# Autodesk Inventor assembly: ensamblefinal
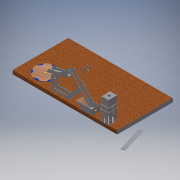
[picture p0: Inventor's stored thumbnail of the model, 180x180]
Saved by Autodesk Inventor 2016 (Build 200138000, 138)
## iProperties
Created: 2016-06
Part Number: ensamblefinal
Material: Genérico
Document SubType Name: Assembly
Designer: adm
Author: adm
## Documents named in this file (13)
- C:\Users\adm\Desktop\el ultimo\ensamblefinal.iam
- C:\Users\adm\Desktop\el ultimo\SOPORTE1.ipt
- C:\Users\adm\Desktop\el ultimo\soporte de rodillos(7.5mm).ipt
- C:\Users\adm\Desktop\el ultimo\soporte3s.ipt
- C:\Users\adm\Desktop\el ultimo\soporte2 de faja.ipt
- C:\Users\adm\Desktop\el ultimo\tablero.ipt
- C:\Users\adm\Desktop\el ultimo\rampa.ipt
- C:\Users\adm\Desktop\el ultimo\caja de motor de faja.ipt
- C:\Users\adm\Desktop\el ultimo\caja de motor de faja2.ipt
- C:\Users\adm\Desktop\ensamble33.iam
- C:\Users\adm\Desktop\recepcion 2\Ensamblaje2.iam
- C:\Users\adm\Desktop\Soportes\Ensamblaje1.iam
- C:\Users\adm\Desktop\recepcion 1\Ensamblaje1.iam
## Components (13 placed, 11 different names)
1. SOPORTE1:1
2. soporte de rodillos(7.5mm):2 — Coincidencia:2, Coincidencia:3, Nivelación:1, Nivelación:2, Coincidencia:13
3. soporte3s:1 — Coincidencia:4, Nivelación:3, Coincidencia:7, Coincidencia:9, Coincidencia:10, Coincidencia:12
4. soporte2 de faja:1 — Coincidencia:2, Coincidencia:3, Nivelación:3, Coincidencia:6, Nivelación:5, Coincidencia:8, Coincidencia:13
5. soporte de rodillos(7.5mm):3 — Nivelación:1, Nivelación:2, Coincidencia:4, Coincidencia:12
6. tablero:1 — Coincidencia:6, Coincidencia:11, Nivelación:6, Coincidencia:14, Nivelación:7
7. rampa:1 — Nivelación:5, Coincidencia:7, Coincidencia:8, Coincidencia:9, Coincidencia:10
8. caja de motor de faja:1
9. caja de motor de faja2:1
10. ensamble33:1 [sub-assembly]
11. Ensamblaje2:1 [sub-assembly] — Coincidencia:11, Nivelación:6
12. Ensamblaje1:1 [sub-assembly] — Coincidencia:14, Coincidencia:15, Nivelación:7, Coincidencia:16, Coincidencia:17
13. Ensamblaje1:2 [sub-assembly] — Coincidencia:15, Coincidencia:16, Coincidencia:17
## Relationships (21: Mate 15, Flush 6)
- Coincidencia:2 [Mate]: soporte de rodillos(7.5mm):2 ↔ soporte2 de faja:1
- Coincidencia:3 [Mate]: soporte de rodillos(7.5mm):2 ↔ soporte2 de faja:1
- Nivelación:1 [Flush]: soporte de rodillos(7.5mm):2 ↔ soporte de rodillos(7.5mm):3
- Nivelación:2 [Flush]: soporte de rodillos(7.5mm):2 ↔ soporte de rodillos(7.5mm):3
- Coincidencia:4 [Mate]: soporte3s:1 ↔ soporte de rodillos(7.5mm):3
- Nivelación:3 [Flush]: soporte3s:1 ↔ soporte2 de faja:1
- Coincidencia:6 [Mate]: soporte2 de faja:1 ↔ tablero:1
- Nivelación:5 [Flush]: soporte2 de faja:1 ↔ rampa:1
- Coincidencia:7 [Mate]: soporte3s:1 ↔ rampa:1
- Coincidencia:8 [Mate]: soporte2 de faja:1 ↔ rampa:1
- Coincidencia:9 [Mate]: soporte3s:1 ↔ rampa:1
- Coincidencia:10 [Mate]: soporte3s:1 ↔ rampa:1
- Coincidencia:11 [Mate]: tablero:1 ↔ Ensamblaje2:1
- Nivelación:6 [Flush]: tablero:1 ↔ Ensamblaje2:1
- Coincidencia:12 [Mate]: soporte3s:1 ↔ soporte de rodillos(7.5mm):3
- Coincidencia:13 [Mate]: soporte de rodillos(7.5mm):2 ↔ soporte2 de faja:1
- Coincidencia:14 [Mate]: tablero:1 ↔ Ensamblaje1:1
- Coincidencia:15 [Mate]: Ensamblaje1:1 ↔ Ensamblaje1:2
- Nivelación:7 [Flush]: tablero:1 ↔ Ensamblaje1:1
- Coincidencia:16 [Mate]: Ensamblaje1:1 ↔ Ensamblaje1:2
- Coincidencia:17 [Mate]: Ensamblaje1:1 ↔ Ensamblaje1:2
